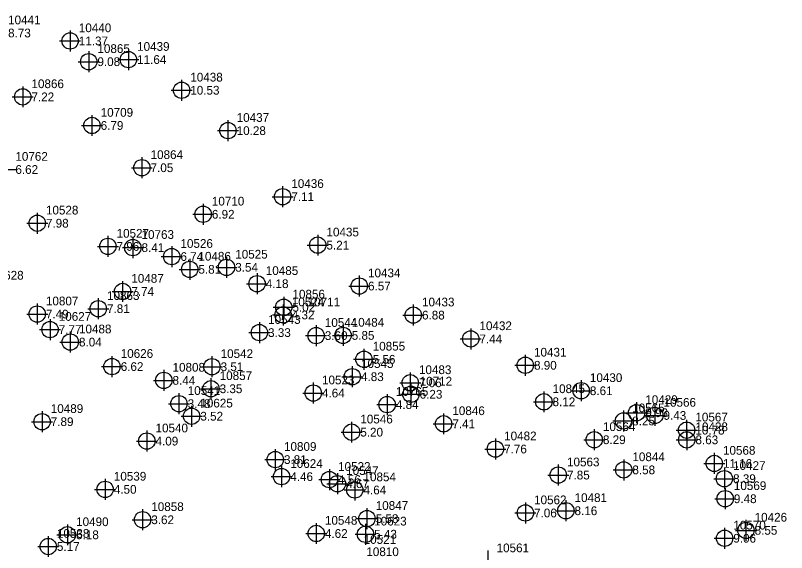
# Model space of a CAD drawing. Extents: x 2062781 to 2066835, y 358981 to 366501.
# Drawn here: x 2064858.6 to 2065079.6, y 361705.9 to 361859.7 of the extents above; entities that cross this region are included whole.
import ezdxf

# ---------------------------------------------------------------- set-up
doc = ezdxf.new("R2010")
doc.units = 0
for name, color, linetype in [('COGO Default Point Elevation', 7, 'Continuous'), ('COGO Default Point Number', 7, 'Continuous'), ('Exist DTM Regular Point Underwater CELL', 7, 'Continuous')]:
    doc.layers.add(name, color=color, linetype=linetype)

msp = doc.modelspace()

# ---------------------------------------------------------------- linework, layer by layer
at = {"layer": 'Exist DTM Regular Point Underwater CELL'}
for points in [[(2064874.27, 361855.44), (2064874.27, 361852.44)], [(2064871.27, 361852.44), (2064874.27, 361852.44)], [(2064874.27, 361852.44), (2064877.27, 361852.44)], [(2064874.27, 361852.44), (2064874.27, 361849.44)], [(2064879.6, 361849.49), (2064879.6, 361846.49)], [(2064890.97, 361850.1), (2064890.97, 361847.1)], [(2064876.6, 361846.49), (2064879.6, 361846.49)], [(2064879.6, 361846.49), (2064882.6, 361846.49)], [(2064879.6, 361846.49), (2064879.6, 361843.49)], [(2064887.97, 361847.1), (2064890.97, 361847.1)], [(2064890.97, 361847.1), (2064893.97, 361847.1)], [(2064890.97, 361847.1), (2064890.97, 361844.1)], [(2064860.7, 361839.42), (2064860.7, 361836.42)], [(2064906.21, 361841.31), (2064906.21, 361838.31)], [(2064903.21, 361838.31), (2064906.21, 361838.31)], [(2064906.21, 361838.31), (2064909.21, 361838.31)], [(2064906.21, 361838.31), (2064906.21, 361835.31)], [(2064857.7, 361836.42), (2064860.7, 361836.42)], [(2064860.7, 361836.42), (2064863.7, 361836.42)], [(2064860.7, 361836.42), (2064860.7, 361833.42)], [(2064880.53, 361831.22), (2064880.53, 361828.22)], [(2064877.53, 361828.22), (2064880.53, 361828.22)], [(2064880.53, 361828.22), (2064883.53, 361828.22)], [(2064880.53, 361828.22), (2064880.53, 361825.22)], [(2064919.5, 361829.75), (2064919.5, 361826.75)], [(2064916.5, 361826.75), (2064919.5, 361826.75)], [(2064919.5, 361826.75), (2064922.5, 361826.75)], [(2064919.5, 361826.75), (2064919.5, 361823.75)], [(2064894.83, 361819.12), (2064894.83, 361816.12)], [(2064856.09, 361815.61), (2064859.09, 361815.61)], [(2064891.83, 361816.12), (2064894.83, 361816.12)], [(2064894.83, 361816.12), (2064897.83, 361816.12)], [(2064894.83, 361816.12), (2064894.83, 361813.12)], [(2064935.16, 361810.83), (2064935.16, 361807.83)], [(2064932.16, 361807.83), (2064935.16, 361807.83)], [(2064935.16, 361807.83), (2064938.16, 361807.83)], [(2064935.16, 361807.83), (2064935.16, 361804.83)], [(2064912.39, 361805.79), (2064912.39, 361802.79)], [(2064864.85, 361803.23), (2064864.85, 361800.23)], [(2064909.39, 361802.79), (2064912.39, 361802.79)], [(2064912.39, 361802.79), (2064915.39, 361802.79)], [(2064912.39, 361802.79), (2064912.39, 361799.79)], [(2064861.85, 361800.23), (2064864.85, 361800.23)], [(2064864.85, 361800.23), (2064867.85, 361800.23)], [(2064864.85, 361800.23), (2064864.85, 361797.23)], [(2064885.09, 361796.59), (2064885.09, 361793.59)], [(2064892.24, 361796.24), (2064892.24, 361793.24)], [(2064945.23, 361796.95), (2064945.23, 361793.95)], [(2064882.09, 361793.59), (2064885.09, 361793.59)], [(2064885.09, 361793.59), (2064888.09, 361793.59)], [(2064885.09, 361793.59), (2064885.09, 361790.59)], [(2064889.24, 361793.24), (2064892.24, 361793.24)], [(2064892.24, 361793.24), (2064895.24, 361793.24)], [(2064892.24, 361793.24), (2064892.24, 361790.24)], [(2064903.39, 361793.68), (2064903.39, 361790.68)], [(2064942.23, 361793.95), (2064945.23, 361793.95)], [(2064945.23, 361793.95), (2064948.23, 361793.95)], [(2064945.23, 361793.95), (2064945.23, 361790.95)], [(2064900.39, 361790.68), (2064903.39, 361790.68)], [(2064903.39, 361790.68), (2064906.39, 361790.68)], [(2064903.39, 361790.68), (2064903.39, 361787.68)], [(2064919.09, 361790.59), (2064919.09, 361787.59)], [(2064908.54, 361790.02), (2064908.54, 361787.02)], [(2064905.54, 361787.02), (2064908.54, 361787.02)], [(2064908.54, 361787.02), (2064911.54, 361787.02)], [(2064908.54, 361787.02), (2064908.54, 361784.02)], [(2064916.09, 361787.59), (2064919.09, 361787.59)], [(2064919.09, 361787.59), (2064922.09, 361787.59)], [(2064919.09, 361787.59), (2064919.09, 361784.59)], [(2064927.84, 361785.91), (2064927.84, 361782.91)], [(2064957.14, 361785.24), (2064957.14, 361782.24)], [(2064889.31, 361783.68), (2064889.31, 361780.68)], [(2064924.84, 361782.91), (2064927.84, 361782.91)], [(2064927.84, 361782.91), (2064930.84, 361782.91)], [(2064927.84, 361782.91), (2064927.84, 361779.91)], [(2064954.14, 361782.24), (2064957.14, 361782.24)], [(2064957.14, 361782.24), (2064960.14, 361782.24)], [(2064957.14, 361782.24), (2064957.14, 361779.24)], [(2064886.31, 361780.68), (2064889.31, 361780.68)], [(2064889.31, 361780.68), (2064892.31, 361780.68)], [(2064889.31, 361780.68), (2064889.31, 361777.68)], [(2064882.35, 361778.75), (2064882.35, 361775.75)], [(2064935.49, 361779.17), (2064935.49, 361776.17)], [(2064864.84, 361777.21), (2064864.84, 361774.21)], [(2064879.35, 361775.75), (2064882.35, 361775.75)], [(2064882.35, 361775.75), (2064885.35, 361775.75)], [(2064882.35, 361775.75), (2064882.35, 361772.75)], [(2064932.49, 361776.17), (2064935.49, 361776.17)], [(2064935.29, 361776.96), (2064935.29, 361773.96)], [(2064935.49, 361776.17), (2064938.49, 361776.17)], [(2064935.49, 361776.17), (2064935.49, 361773.17)], [(2064972.61, 361776.91), (2064972.61, 361773.91)], [(2064861.84, 361774.21), (2064864.84, 361774.21)], [(2064864.84, 361774.21), (2064867.84, 361774.21)], [(2064864.84, 361774.21), (2064864.84, 361771.21)], [(2064932.29, 361773.96), (2064935.29, 361773.96)], [(2064935.29, 361773.96), (2064938.29, 361773.96)], [(2064935.29, 361773.96), (2064935.29, 361770.96)], [(2064969.61, 361773.91), (2064972.61, 361773.91)], [(2064972.61, 361773.91), (2064975.61, 361773.91)], [(2064972.61, 361773.91), (2064972.61, 361770.91)], [(2064868.51, 361772.77), (2064868.51, 361769.77)], [(2064928.5, 361771.9), (2064928.5, 361768.9)], [(2064944.76, 361771.03), (2064944.76, 361768.03)], [(2064952.47, 361771.1), (2064952.47, 361768.1)], [(2064865.51, 361769.77), (2064868.51, 361769.77)], [(2064868.51, 361769.77), (2064871.51, 361769.77)], [(2064868.51, 361769.77), (2064868.51, 361766.77)], [(2064874.32, 361769.19), (2064874.32, 361766.19)], [(2064925.5, 361768.9), (2064928.5, 361768.9)], [(2064928.5, 361768.9), (2064931.5, 361768.9)], [(2064928.5, 361768.9), (2064928.5, 361765.9)], [(2064989.07, 361770.11), (2064989.07, 361767.11)], [(2064941.76, 361768.03), (2064944.76, 361768.03)], [(2064944.76, 361768.03), (2064947.76, 361768.03)], [(2064944.76, 361768.03), (2064944.76, 361765.03)], [(2064949.47, 361768.1), (2064952.47, 361768.1)], [(2064952.47, 361768.1), (2064955.47, 361768.1)], [(2064952.47, 361768.1), (2064952.47, 361765.1)], [(2064986.07, 361767.11), (2064989.07, 361767.11)], [(2064989.07, 361767.11), (2064992.07, 361767.11)], [(2064989.07, 361767.11), (2064989.07, 361764.11)], [(2064871.32, 361766.19), (2064874.32, 361766.19)], [(2064874.32, 361766.19), (2064877.32, 361766.19)], [(2064874.32, 361766.19), (2064874.32, 361763.19)], [(2064958.48, 361764.26), (2064958.48, 361761.26)], [(2064886.27, 361762.17), (2064886.27, 361759.17)], [(2064914.9, 361762.12), (2064914.9, 361759.12)], [(2065004.7, 361762.54), (2065004.7, 361759.54)], [(2064955.48, 361761.26), (2064958.48, 361761.26)], [(2064958.48, 361761.26), (2064961.48, 361761.26)], [(2064958.48, 361761.26), (2064958.48, 361758.26)], [(2064883.27, 361759.17), (2064886.27, 361759.17)], [(2064886.27, 361759.17), (2064889.27, 361759.17)], [(2064886.27, 361759.17), (2064886.27, 361756.17)], [(2064901.12, 361758.22), (2064901.12, 361755.22)], [(2064911.9, 361759.12), (2064914.9, 361759.12)], [(2064914.9, 361759.12), (2064917.9, 361759.12)], [(2064914.9, 361759.12), (2064914.9, 361756.12)], [(2064955.13, 361759.26), (2064955.13, 361756.26)], [(2064971.73, 361757.52), (2064971.73, 361754.52)], [(2065001.7, 361759.54), (2065004.7, 361759.54)], [(2065004.7, 361759.54), (2065007.7, 361759.54)], [(2065004.7, 361759.54), (2065004.7, 361756.54)], [(2064898.12, 361755.22), (2064901.12, 361755.22)], [(2064901.12, 361755.22), (2064904.12, 361755.22)], [(2064901.12, 361755.22), (2064901.12, 361752.22)], [(2064914.63, 361755.81), (2064914.63, 361752.81)], [(2064952.13, 361756.26), (2064955.13, 361756.26)], [(2064955.13, 361756.26), (2064958.13, 361756.26)], [(2064955.13, 361756.26), (2064955.13, 361753.26)], [(2065020.71, 361755.25), (2065020.71, 361752.25)], [(2064943.95, 361754.59), (2064943.95, 361751.59)], [(2064968.73, 361754.52), (2064971.73, 361754.52)], [(2064971.73, 361754.52), (2064974.73, 361754.52)], [(2064971.73, 361754.52), (2064971.73, 361751.52)], [(2064971.93, 361754.24), (2064971.93, 361751.24)], [(2064905.47, 361751.55), (2064905.47, 361748.55)], [(2064911.63, 361752.81), (2064914.63, 361752.81)], [(2064914.63, 361752.81), (2064917.63, 361752.81)], [(2064914.63, 361752.81), (2064914.63, 361749.81)], [(2064940.95, 361751.59), (2064943.95, 361751.59)], [(2064943.95, 361751.59), (2064946.95, 361751.59)], [(2064943.95, 361751.59), (2064943.95, 361748.59)], [(2064965.12, 361751.28), (2064965.12, 361748.28)], [(2064968.93, 361751.24), (2064971.93, 361751.24)], [(2064971.93, 361751.24), (2064974.93, 361751.24)], [(2064971.93, 361751.24), (2064971.93, 361748.24)], [(2065010.02, 361752.08), (2065010.02, 361749.08)], [(2065017.71, 361752.25), (2065020.71, 361752.25)], [(2065020.71, 361752.25), (2065023.71, 361752.25)], [(2065020.71, 361752.25), (2065020.71, 361749.25)], [(2065007.02, 361749.08), (2065010.02, 361749.08)], [(2065010.02, 361749.08), (2065013.02, 361749.08)], [(2065010.02, 361749.08), (2065010.02, 361746.08)], [(2065036.59, 361748.95), (2065036.59, 361745.95)], [(2064866.23, 361746.39), (2064866.23, 361743.39)], [(2064902.47, 361748.55), (2064905.47, 361748.55)], [(2064905.47, 361748.55), (2064908.47, 361748.55)], [(2064905.47, 361748.55), (2064905.47, 361745.55)], [(2064909.09, 361747.96), (2064909.09, 361744.96)], [(2064962.12, 361748.28), (2064965.12, 361748.28)], [(2064965.12, 361748.28), (2064968.12, 361748.28)], [(2064965.12, 361748.28), (2064965.12, 361745.28)], [(2065032.83, 361746.59), (2065032.83, 361743.59)], [(2065041.82, 361748.18), (2065041.82, 361745.18)], [(2064906.09, 361744.96), (2064909.09, 361744.96)], [(2064909.09, 361744.96), (2064912.09, 361744.96)], [(2064909.09, 361744.96), (2064909.09, 361741.96)], [(2064981.3, 361745.78), (2064981.3, 361742.78)], [(2065033.59, 361745.95), (2065036.59, 361745.95)], [(2065036.59, 361745.95), (2065039.59, 361745.95)], [(2065036.59, 361745.95), (2065036.59, 361742.95)], [(2065038.82, 361745.18), (2065041.82, 361745.18)], [(2065041.82, 361745.18), (2065044.82, 361745.18)], [(2065041.82, 361745.18), (2065041.82, 361742.18)], [(2064863.23, 361743.39), (2064866.23, 361743.39)], [(2064866.23, 361743.39), (2064869.23, 361743.39)], [(2064866.23, 361743.39), (2064866.23, 361740.39)], [(2064954.93, 361743.39), (2064954.93, 361740.39)], [(2064978.3, 361742.78), (2064981.3, 361742.78)], [(2064981.3, 361742.78), (2064984.3, 361742.78)], [(2064981.3, 361742.78), (2064981.3, 361739.78)], [(2065029.83, 361743.59), (2065032.83, 361743.59)], [(2065032.83, 361743.59), (2065035.83, 361743.59)], [(2065032.83, 361743.59), (2065032.83, 361740.59)], [(2065050.94, 361743.96), (2065050.94, 361740.96)], [(2064896.25, 361740.83), (2064896.25, 361737.83)], [(2064951.93, 361740.39), (2064954.93, 361740.39)], [(2064954.93, 361740.39), (2064957.93, 361740.39)], [(2064954.93, 361740.39), (2064954.93, 361737.39)], [(2065024.45, 361741.21), (2065024.45, 361738.21)], [(2065047.94, 361740.96), (2065050.94, 361740.96)], [(2065050.94, 361740.96), (2065053.94, 361740.96)], [(2065050.94, 361740.96), (2065050.94, 361737.96)], [(2065050.97, 361741.19), (2065050.97, 361738.19)], [(2064893.25, 361737.83), (2064896.25, 361737.83)], [(2064896.25, 361737.83), (2064899.25, 361737.83)], [(2064896.25, 361737.83), (2064896.25, 361734.83)], [(2064996.14, 361738.56), (2064996.14, 361735.56)], [(2065021.45, 361738.21), (2065024.45, 361738.21)], [(2065024.45, 361738.21), (2065027.45, 361738.21)], [(2065024.45, 361738.21), (2065024.45, 361735.21)], [(2065047.97, 361738.19), (2065050.97, 361738.19)], [(2065050.97, 361738.19), (2065053.97, 361738.19)], [(2065050.97, 361738.19), (2065050.97, 361735.19)], [(2064933.06, 361735.52), (2064933.06, 361732.52)], [(2064993.14, 361735.56), (2064996.14, 361735.56)], [(2064996.14, 361735.56), (2064999.14, 361735.56)], [(2064996.14, 361735.56), (2064996.14, 361732.56)], [(2065058.85, 361734.43), (2065058.85, 361731.43)], [(2064930.06, 361732.52), (2064933.06, 361732.52)], [(2064933.06, 361732.52), (2064936.06, 361732.52)], [(2064933.06, 361732.52), (2064933.06, 361729.52)], [(2065014.16, 361731.1), (2065014.16, 361728.1)], [(2065032.89, 361732.59), (2065032.89, 361729.59)], [(2065055.85, 361731.43), (2065058.85, 361731.43)], [(2065058.85, 361731.43), (2065061.85, 361731.43)], [(2065058.85, 361731.43), (2065058.85, 361728.43)], [(2064934.86, 361730.65), (2064934.86, 361727.65)], [(2064948.56, 361729.81), (2064948.56, 361726.81)], [(2065029.89, 361729.59), (2065032.89, 361729.59)], [(2065032.89, 361729.59), (2065035.89, 361729.59)], [(2065032.89, 361729.59), (2065032.89, 361726.59)], [(2065061.75, 361730.07), (2065061.75, 361727.07)], [(2064884.3, 361727.01), (2064884.3, 361724.01)], [(2064931.86, 361727.65), (2064934.86, 361727.65)], [(2064934.86, 361727.65), (2064937.86, 361727.65)], [(2064934.86, 361727.65), (2064934.86, 361724.65)], [(2064945.56, 361726.81), (2064948.56, 361726.81)], [(2064948.56, 361726.81), (2064951.56, 361726.81)], [(2064948.56, 361726.81), (2064948.56, 361723.81)], [(2064950.88, 361728.63), (2064950.88, 361725.63)], [(2064955.84, 361726.83), (2064955.84, 361723.83)], [(2065011.16, 361728.1), (2065014.16, 361728.1)], [(2065014.16, 361728.1), (2065017.16, 361728.1)], [(2065014.16, 361728.1), (2065014.16, 361725.1)], [(2065058.75, 361727.07), (2065061.75, 361727.07)], [(2065061.75, 361727.07), (2065064.75, 361727.07)], [(2065061.75, 361727.07), (2065061.75, 361724.07)], [(2064947.88, 361725.63), (2064950.88, 361725.63)], [(2064950.88, 361725.63), (2064953.88, 361725.63)], [(2064950.88, 361725.63), (2064950.88, 361722.63)], [(2065061.97, 361724.32), (2065061.97, 361721.32)], [(2064881.3, 361724.01), (2064884.3, 361724.01)], [(2064884.3, 361724.01), (2064887.3, 361724.01)], [(2064884.3, 361724.01), (2064884.3, 361721.01)], [(2064952.84, 361723.83), (2064955.84, 361723.83)], [(2064955.84, 361723.83), (2064958.84, 361723.83)], [(2064955.84, 361723.83), (2064955.84, 361720.83)], [(2065004.72, 361720.25), (2065004.72, 361717.25)], [(2065016.32, 361720.88), (2065016.32, 361717.88)], [(2065058.97, 361721.32), (2065061.97, 361721.32)], [(2065061.97, 361721.32), (2065064.97, 361721.32)], [(2065061.97, 361721.32), (2065061.97, 361718.32)], [(2064895.03, 361718.3), (2064895.03, 361715.3)], [(2064959.34, 361718.63), (2064959.34, 361715.63)], [(2065013.32, 361717.88), (2065016.32, 361717.88)], [(2065016.32, 361717.88), (2065019.32, 361717.88)], [(2065016.32, 361717.88), (2065016.32, 361714.88)], [(2064956.34, 361715.63), (2064959.34, 361715.63)], [(2064959.34, 361715.63), (2064962.34, 361715.63)], [(2064959.34, 361715.63), (2064959.34, 361712.63)], [(2065001.72, 361717.25), (2065004.72, 361717.25)], [(2065004.72, 361717.25), (2065007.72, 361717.25)], [(2065004.72, 361717.25), (2065004.72, 361714.25)], [(2064873.49, 361713.99), (2064873.49, 361710.99)], [(2064892.03, 361715.3), (2064895.03, 361715.3)], [(2064895.03, 361715.3), (2064898.03, 361715.3)], [(2064895.03, 361715.3), (2064895.03, 361712.3)], [(2064944.79, 361714.37), (2064944.79, 361711.37)], [(2064958.91, 361714.16), (2064958.91, 361711.16)], [(2065067.92, 361715.26), (2065067.92, 361712.26)], [(2064941.79, 361711.37), (2064944.79, 361711.37)], [(2064944.79, 361711.37), (2064947.79, 361711.37)], [(2064944.79, 361711.37), (2064944.79, 361708.37)], [(2064955.91, 361711.16), (2064958.91, 361711.16)], [(2064958.91, 361711.16), (2064961.91, 361711.16)], [(2064958.91, 361711.16), (2064958.91, 361708.16)], [(2065061.81, 361713), (2065061.81, 361710)], [(2065064.92, 361712.26), (2065067.92, 361712.26)], [(2065067.92, 361712.26), (2065070.92, 361712.26)], [(2065067.92, 361712.26), (2065067.92, 361709.26)], [(2064867.99, 361710.64), (2064867.99, 361707.64)], [(2064870.49, 361710.99), (2064873.49, 361710.99)], [(2064873.49, 361710.99), (2064876.49, 361710.99)], [(2064873.49, 361710.99), (2064873.49, 361707.99)], [(2065058.81, 361710), (2065061.81, 361710)], [(2065061.81, 361710), (2065064.81, 361710)], [(2065061.81, 361710), (2065061.81, 361707)], [(2064864.99, 361707.64), (2064867.99, 361707.64)], [(2064867.99, 361707.64), (2064870.99, 361707.64)], [(2064867.99, 361707.64), (2064867.99, 361704.64)], [(2064993.98, 361706.5), (2064993.98, 361703.5)]]:
    msp.add_lwpolyline(points, dxfattribs=at)
for centre in [(2064874.27, 361852.44), (2064879.6, 361846.49), (2064890.97, 361847.1), (2064906.21, 361838.31), (2064860.7, 361836.42), (2064880.53, 361828.22), (2064919.5, 361826.75), (2064894.83, 361816.12), (2064935.16, 361807.83), (2064912.39, 361802.79), (2064864.85, 361800.23), (2064885.09, 361793.59), (2064892.24, 361793.24), (2064945.23, 361793.95), (2064903.39, 361790.68), (2064908.54, 361787.02), (2064919.09, 361787.59), (2064927.84, 361782.91), (2064957.14, 361782.24), (2064889.31, 361780.68), (2064882.35, 361775.75), (2064935.49, 361776.17), (2064864.84, 361774.21), (2064935.29, 361773.96), (2064972.61, 361773.91), (2064868.51, 361769.77), (2064928.5, 361768.9), (2064874.32, 361766.19), (2064944.76, 361768.03), (2064952.47, 361768.1), (2064989.07, 361767.11), (2064958.48, 361761.26), (2065004.7, 361759.54), (2064886.27, 361759.17), (2064914.9, 361759.12), (2064901.12, 361755.22), (2064955.13, 361756.26), (2064971.73, 361754.52), (2064914.63, 361752.81), (2064943.95, 361751.59), (2064971.93, 361751.24), (2065020.71, 361752.25), (2064905.47, 361748.55), (2065010.02, 361749.08), (2064965.12, 361748.28), (2064909.09, 361744.96), (2065036.59, 361745.95), (2065041.82, 361745.18), (2064866.23, 361743.39), (2064981.3, 361742.78), (2065032.83, 361743.59), (2064954.93, 361740.39), (2065050.94, 361740.96), (2064896.25, 361737.83), (2065024.45, 361738.21), (2065050.97, 361738.19), (2064996.14, 361735.56), (2064933.06, 361732.52), (2065058.85, 361731.43), (2065032.89, 361729.59), (2064934.86, 361727.65), (2064948.56, 361726.81), (2065014.16, 361728.1), (2065061.75, 361727.07), (2064950.88, 361725.63), (2064884.3, 361724.01), (2064955.84, 361723.83), (2065061.97, 361721.32), (2065016.32, 361717.88), (2064959.34, 361715.63), (2065004.72, 361717.25), (2064895.03, 361715.3), (2064873.49, 361710.99), (2064944.79, 361711.37), (2064958.91, 361711.16), (2065067.92, 361712.26), (2065061.81, 361710), (2064867.99, 361707.64)]:
    msp.add_circle(centre, 2.34, dxfattribs=at)

# ---------------------------------------------------------------- texts
at = {"layer": 'COGO Default Point Elevation'}
for s, p in [('8.73', (2064856.5, 361853.45)), ('11.37', (2064876.77, 361851.19)), ('11.64', (2064893.47, 361845.85)), ('9.08', (2064882.1, 361845.24)), ('10.53', (2064908.71, 361837.06)), ('7.22', (2064863.2, 361835.17)), ('6.79', (2064883.03, 361826.97)), ('10.28', (2064922, 361825.5)), ('7.05', (2064897.33, 361814.87)), ('6.62', (2064858.59, 361814.36)), ('7.11', (2064937.66, 361806.58)), ('6.92', (2064914.89, 361801.54)), ('7.98', (2064867.35, 361798.98)), ('5.21', (2064947.73, 361792.7)), ('7.96', (2064887.59, 361792.34)), ('8.41', (2064894.74, 361791.99)), ('6.74', (2064905.89, 361789.43)), ('3.54', (2064921.59, 361786.35)), ('5.81', (2064911.04, 361785.77)), ('4.18', (2064930.34, 361781.66)), ('7.74', (2064891.81, 361779.43)), ('6.57', (2064959.64, 361780.99)), ('5.02', (2064937.99, 361774.92)), ('7.49', (2064867.34, 361772.96)), ('7.81', (2064884.85, 361774.5)), ('4.32', (2064937.79, 361772.71)), ('6.88', (2064975.11, 361772.66)), ('7.77', (2064871.01, 361768.53)), ('3.33', (2064931, 361767.65)), ('3.60', (2064947.26, 361766.79)), ('5.85', (2064954.97, 361766.85)), ('8.04', (2064876.82, 361764.94)), ('7.44', (2064991.57, 361765.86)), ('5.56', (2064960.98, 361760.01)), ('6.62', (2064888.77, 361757.92)), ('3.51', (2064917.4, 361757.88)), ('8.90', (2065007.2, 361758.29)), ('4.83', (2064957.63, 361755.02)), ('8.44', (2064903.62, 361753.97)), ('7.06', (2064974.23, 361753.27)), ('3.35', (2064917.13, 361751.57)), ('8.61', (2065023.21, 361751)), ('4.64', (2064946.45, 361750.34)), ('6.23', (2064974.43, 361749.99)), ('3.48', (2064907.97, 361747.3)), ('4.84', (2064967.62, 361747.03)), ('8.12', (2065012.52, 361747.83)), ('9.93', (2065039.09, 361744.7)), ('9.43', (2065044.32, 361743.93)), ('7.89', (2064868.73, 361742.14)), ('3.52', (2064911.59, 361743.71)), ('8.25', (2065035.33, 361742.34)), ('7.41', (2064983.8, 361741.53)), ('10.78', (2065053.44, 361739.71)), ('5.20', (2064957.43, 361739.14)), ('4.09', (2064898.75, 361736.58)), ('8.29', (2065026.95, 361736.97)), ('8.63', (2065053.47, 361736.94)), ('7.76', (2064998.64, 361734.31)), ('3.81', (2064935.56, 361731.28)), ('11.16', (2065061.35, 361730.18)), ('4.46', (2064937.36, 361726.4)), ('7.85', (2065016.66, 361726.85)), ('8.58', (2065035.39, 361728.34)), ('4.56', (2064951.06, 361725.56)), ('4.67', (2064953.38, 361724.38)), ('8.39', (2065064.25, 361725.82)), ('4.50', (2064886.8, 361722.76)), ('4.64', (2064958.34, 361722.58)), ('9.48', (2065064.47, 361720.07)), ('7.06', (2065007.22, 361716)), ('8.16', (2065018.82, 361716.63)), ('3.62', (2064897.53, 361714.05)), ('5.58', (2064961.84, 361714.38)), ('8.55', (2065070.42, 361711.02)), ('5.18', (2064875.99, 361709.74)), ('4.62', (2064947.29, 361710.12)), ('5.43', (2064961.41, 361709.91)), ('9.06', (2065064.31, 361708.75)), ('5.17', (2064870.49, 361706.39))]:
    msp.add_text(s, height=2.5, dxfattribs=at).set_placement(p)
at = {"layer": 'COGO Default Point Number'}
for s, p in [('10441', (2064856.5, 361857.2)), ('10440', (2064876.77, 361854.94)), ('10865', (2064882.1, 361848.99)), ('10439', (2064893.47, 361849.6)), ('10866', (2064863.2, 361838.92)), ('10438', (2064908.71, 361840.81)), ('10709', (2064883.03, 361830.72)), ('10437', (2064922, 361829.25)), ('10762', (2064858.59, 361818.11)), ('10864', (2064897.33, 361818.62)), ('10436', (2064937.66, 361810.33)), ('10710', (2064914.89, 361805.29)), ('10528', (2064867.35, 361802.73)), ('10527', (2064887.59, 361796.09)), ('10763', (2064894.74, 361795.74)), ('10435', (2064947.73, 361796.45)), ('10526', (2064905.89, 361793.18)), ('10486', (2064911.04, 361789.52)), ('10525', (2064921.59, 361790.1)), ('10628', (2064851.66, 361784.08)), ('10485', (2064930.34, 361785.41)), ('10434', (2064959.64, 361784.74)), ('10487', (2064891.81, 361783.18)), ('10863', (2064884.85, 361778.25)), ('10856', (2064937.99, 361778.67)), ('10807', (2064867.34, 361776.71)), ('10524', (2064937.79, 361776.46)), ('10711', (2064942.34, 361776.42)), ('10433', (2064975.11, 361776.41)), ('10627', (2064871.01, 361772.28)), ('10543', (2064931, 361771.4)), ('10544', (2064947.26, 361770.54)), ('10484', (2064954.97, 361770.6)), ('10488', (2064876.82, 361768.69)), ('10432', (2064991.57, 361769.61)), ('10855', (2064960.98, 361763.76)), ('10626', (2064888.77, 361761.67)), ('10542', (2064917.4, 361761.62)), ('10431', (2065007.2, 361762.04)), ('10808', (2064903.62, 361757.72)), ('10545', (2064957.63, 361758.77)), ('10857', (2064917.13, 361755.32)), ('10483', (2064974.23, 361757.02)), ('10523', (2064946.45, 361754.09)), ('10712', (2064974.43, 361753.74)), ('10430', (2065023.21, 361754.75)), ('10541', (2064907.97, 361751.05)), ('10765', (2064967.62, 361750.78)), ('10845', (2065012.52, 361751.58)), ('10429', (2065039.09, 361748.45)), ('10625', (2064911.59, 361747.46)), ('10565', (2065035.33, 361746.09)), ('10566', (2065044.32, 361747.68)), ('10489', (2064868.73, 361745.89)), ('10846', (2064983.8, 361745.28)), ('10546', (2064957.43, 361742.89)), ('10567', (2065053.44, 361743.46)), ('10540', (2064898.75, 361740.33)), ('10564', (2065026.95, 361740.72)), ('10428', (2065053.47, 361740.69)), ('10482', (2064998.64, 361738.06)), ('10809', (2064935.56, 361735.03)), ('10568', (2065061.35, 361733.93)), ('10563', (2065016.66, 361730.6)), ('10844', (2065035.39, 361732.09)), ('10624', (2064937.36, 361730.15)), ('10522', (2064951.06, 361729.31)), ('10427', (2065064.25, 361729.57)), ('10539', (2064886.8, 361726.51)), ('10547', (2064953.38, 361728.13)), ('10854', (2064958.34, 361726.33)), ('10569', (2065064.47, 361723.82)), ('10562', (2065007.22, 361719.75)), ('10481', (2065018.82, 361720.38)), ('10858', (2064897.53, 361717.8)), ('10847', (2064961.84, 361718.13)), ('10490', (2064875.99, 361713.49)), ('10548', (2064947.29, 361713.88)), ('10623', (2064961.41, 361713.66)), ('10426', (2065070.42, 361714.77)), ('10570', (2065064.31, 361712.5)), ('10538', (2064870.49, 361710.14)), ('10521', (2064958.39, 361708.4)), ('10810', (2064959.16, 361704.9)), ('10561', (2064996.48, 361706))]:
    msp.add_text(s, height=2.5, dxfattribs=at).set_placement(p)

doc.saveas('drawing.dxf')
